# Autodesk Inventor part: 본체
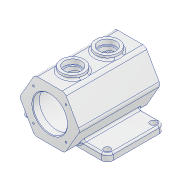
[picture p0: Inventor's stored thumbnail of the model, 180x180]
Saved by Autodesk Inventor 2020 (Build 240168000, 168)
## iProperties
Created: 2021-06
Part Number: 본체
Material: 알루미늄 6061
Document SubType Name: Modeling
Designer: Administrator
Density: 2.7 g/cm^3
Appearance: 알루미늄 - 평지
Mass: 1495.15 g
Surface Area: 1102.35 cm^2
Volume: 553.759 cm^3
Author: Administrator
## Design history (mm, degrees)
sketch "스케치1" dims "d0" = 105
  geometry: L1 (26.25, 45.466)-(52.5, 0); L2 (52.5, 0)-(26.25, -45.466); L3 (26.25, -45.466)-(-26.25, -45.466); L4 (-26.25, -45.466)-(-52.5, 0); L5 (-52.5, 0)-(-26.25, 45.466); L6 (-26.25, 45.466)-(26.25, 45.466); 3 further points
  constraints: 12 end point, 2 coincident, 1 horizontal, 16 other
extrude "돌출1" new body sketch "스케치1" stored distance "d1" = 140; taper "d2" = 0 deg
fillet "모깎기3" dims "d63" = 8
node "작업 평면1"
sketch "스케치2"
  geometry: L1 (75, -55)-(-75, -55); L2 (-75, -55)-(-75, 45); L3 (-75, 45)-(75, 45); L4 (75, 45)-(75, -55); L5 (28.559, 70)-(50.191, 70) reference; 3 further points
  constraints: 8 end point, 2 parallel, 1 horizontal, 1 perpendicular
  dimensions: "d4" = 25 distance between parallel lines of L3 L5; "d5" = 100 distance between parallel lines of L1 L3; "d6" = 150 distance between parallel lines of L2 L4; "d7" = 75 distance from line of point (0, 0) L4
extrude "돌출2" join sketch "스케치2" distance "d8" = 12; taper "d9" = 0 deg
node "작업 평면2"
sketch "스케치3"
  geometry: L1 (-21.631, 70)-(21.631, 70) reference; C1 r 20 at (0, 30); C2 r 20 at (0, -30); 3 further points
  constraints: 2 centre point, 2 vertical alignment, 1 equal radius
  dimensions: "d11" = 40 diameter of C1; "d12" = 40 distance from line of L1 C1.centre; "d13" = 60 distance of C2.centre C1.centre
extrude "돌출3" join sketch "스케치3" stored distance "d14" = 12; taper "d15" = 0 deg
sketch "스케치5"
  geometry: L1 (0, 58)-(0, -58); L2 (0, -58)-(37.5, -58); L3 (37.5, -58)-(37.5, 58); L4 (37.5, 58)-(0, 58); L5 (45.466, 70)-(0, 70) reference; L6 (0, -70)-(45.466, -70) reference; 1 further point
  constraints: 8 end point, 3 perpendicular, 1 vertical, 1 vertical alignment
  dimensions: "d21" = 12 distance between parallel lines of L5 L4; "d22" = 12 distance between parallel lines of L6 L2; "d23" = 75 diameter of L3 L1
revolve "회전1" sketch "스케치5" stored, may be unused: angle "d24" = 90 deg
sketch "스케치6"
  geometry: C1 r 30 at (0, 0); 1 further point
  constraints: 1 centre point, 1 coincident
  dimensions: "d25" = 60 diameter of C1
extrude "돌출4" cut sketch "스케치6" distance "d26" = 12; taper "d27" = 0 deg
sketch "스케치7"
  geometry: C1 r 30 at (0, 0); 2 further points
  constraints: 1 centre point, 1 coincident
  dimensions: "d28" = 60 diameter of C1
extrude "돌출5" cut sketch "스케치7" distance "d29" = 12; taper "d30" = 0 deg
sketch "스케치8"
  geometry: C1 r 20 at (0, 0) reference; C2 r 20 at (0, 60) reference; 3 further points
  constraints: 2 coincident
hole "구멍1" sketch "스케치8" at (0, 0), (0, 60) diameter "d31" = 25; stored, may be unused: countersink angle "d35" = 90 deg, drill point angle "d37" = 0 deg; dims "d32" = 6, "d33" = 30, "d34" = 8, "d36" = 20
sketch "스케치9"
  geometry: L1 (0, 0)-(0, 40); L2 (0, 0)-(-28.284, 28.284); A1 r 40 centre (0, 0) between (0, 40) and (-28.284, 28.284); 2 further points
  constraints: 4 end point, 2 coincident, 2 point on circle, 1 centre point, 1 vertical
  dimensions: "d38" = 80 diameter of A1; "d39" = 45 deg angle of L1 L2
hole "구멍2" sketch "스케치9" at (-28.284, 28.284) diameter "d40" = 3.242; stored, may be unused: countersink angle "d44" = 90 deg, drill point angle "d46" = 120 deg; dims "d41" = 8, "d42" = 30, "d43" = 8, "d45" = 10
sketch "스케치12"
  geometry: 2 further points
  constraints: 1 vertical alignment
  dimensions: "d74" = 40 distance of point (0, 0) point (0, 40)
hole "구멍4" sketch "스케치12" at (0, 40) diameter "d75" = 3.242; stored, may be unused: countersink angle "d79" = 90 deg, drill point angle "d81" = 120 deg; dims "d76" = 8, "d77" = 30, "d78" = 8, "d80" = 10
sketch "스케치10"
  geometry: L1 (-75, -45)-(75, -45) reference; L2 (-75, 55)-(-75, -45) reference; L3 (75, -45)-(75, 55) reference; L4 (75, 55)-(-75, 55) reference; 5 further points
  constraints: 2 horizontal alignment, 2 vertical alignment
  dimensions: "d50" = 10 distance from line of point (-65, -35) L1; "d51" = 10 distance from line of L2 point (-65, -35); "d52" = 10 distance from line of L3 point (65, -35); "d53" = 10 distance from line of L4 point (65, 45)
hole "구멍3" sketch "스케치10" at (-65, -35), (-65, 45), (65, 45), (65, -35) diameter "d54" = 11; stored, may be unused: countersink angle "d58" = 90 deg, drill point angle "d60" = 120 deg; dims "d55" = 8, "d56" = 30, "d57" = 8, "d59" = 10
fillet "모깎기1" dims "d61" = 10
fillet "모깎기4" dims "d64" = 5
fillet "모깎기5" dims "d65" = 3
fillet "모깎기6" dims "d66" = 3
chamfer "모따기1" distance "d67" = 1; stored, may be unused: second distance "d68" = 2, angle "d69" = 45 deg
sketch "스케치11"
  geometry: L1 (-75, 45)-(-75, -35) reference; L2 (-65, -45)-(-32.293, -45) reference; 2 further points
  constraints: 1 other
  dimensions: "d71" = 14 distance from line of L1 point (-61, 5); "d85" = 50 distance from line of L2 point (-61, 5)
feature "엠보싱1" sketch "스케치11" dims "d0" = 105, "d72" = 0.5, "d73" = 0
node "솔리드1"
pattern_circular "원형 패턴1" dims angle "d48" = 360 deg
pattern_circular "원형 패턴2" dims angle "d83" = 360 deg
feature "A9D066F2-1C7D-4E18-AEED-F7BC21143FA4" dims "d54" = 11, "d55" = 8, "d56" = 30, "d57" = 8, "d58" = 90 deg, "d59" = 10, "d60" = 120 deg
other parameters: "d10" = 52.5
